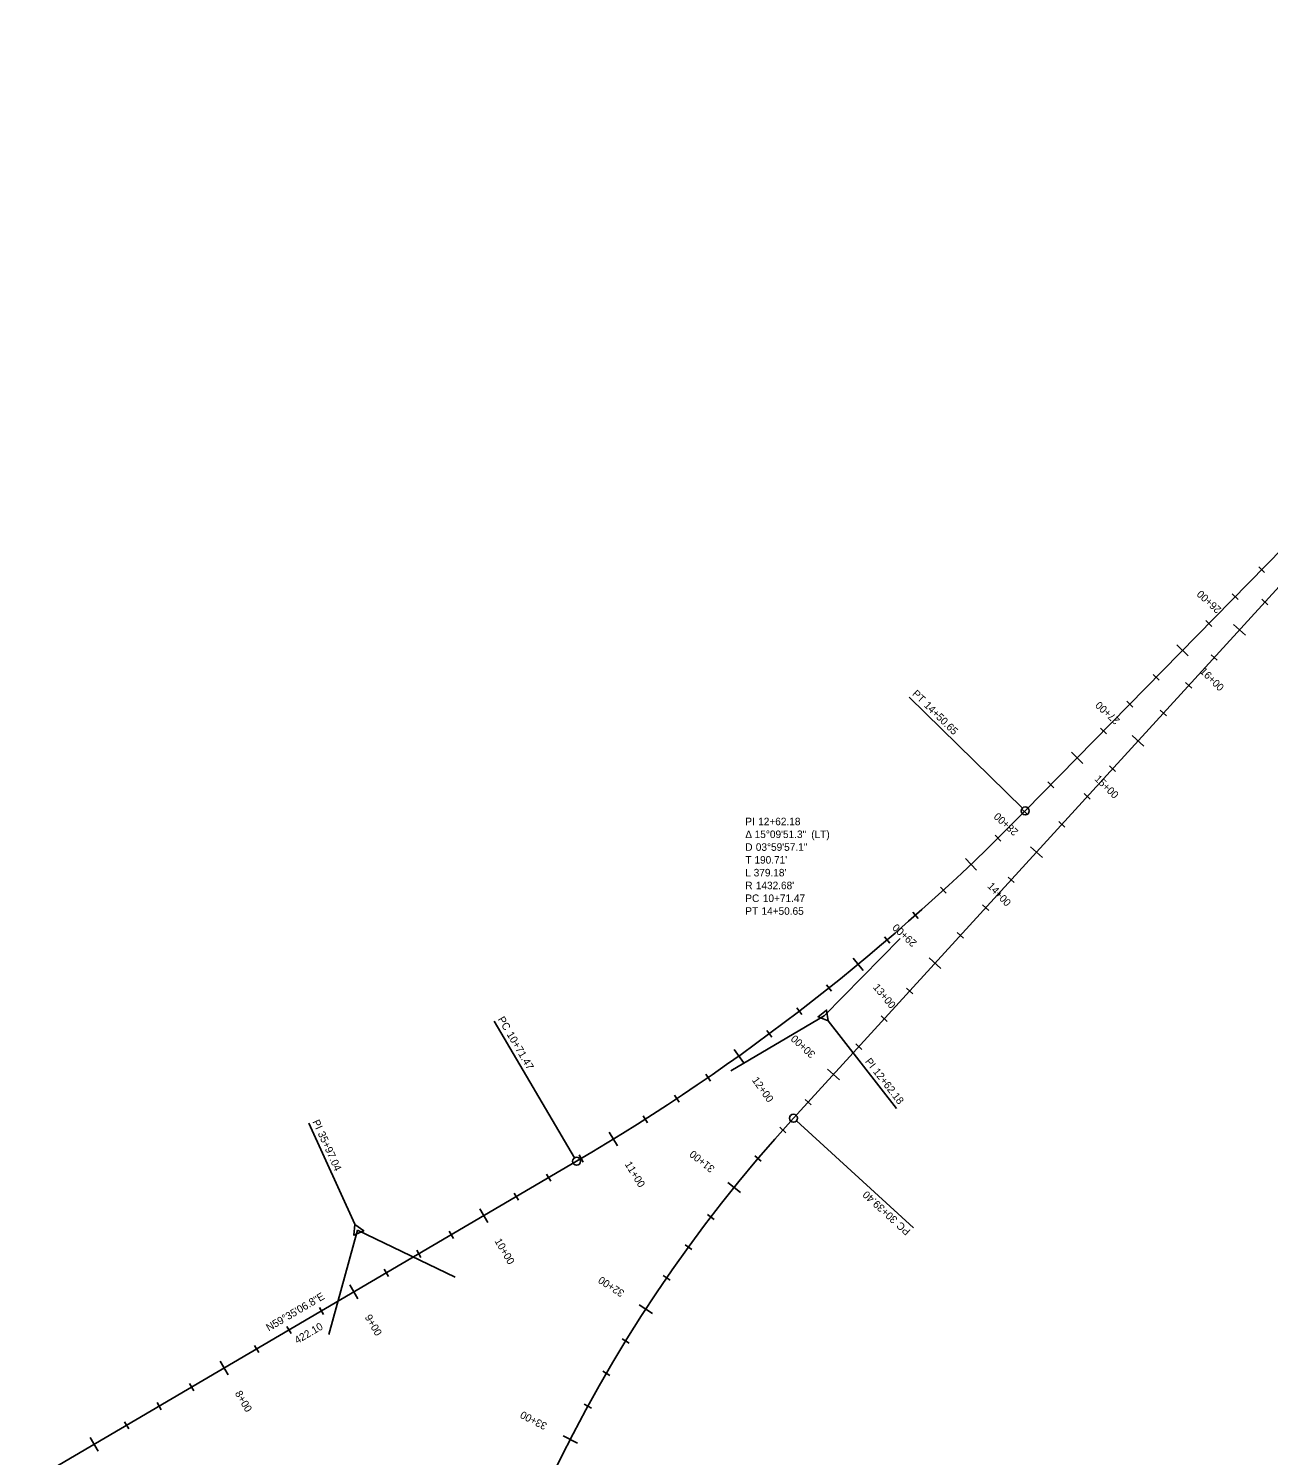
# Model space of a CAD drawing. Extents: x 2300830 to 2307917, y 756066 to 766359.
# Drawn here: x 2302935 to 2303759, y 762132 to 763080 of the extents above; entities that cross this region are included whole.
import ezdxf

# ---------------------------------------------------------------- set-up
doc = ezdxf.new("R2010")
doc.units = 0
for name, color, linetype in [('Default', 7, 'Continuous'), ('Draft_Bearing Label', 7, 'Continuous'), ('Draft_Curve Data Label', 7, 'Continuous'), ('Draft_Station Cardinal Lines', 7, 'Continuous'), ('Draft_Station Cardinal Points', 7, 'Continuous'), ('Draft_Station Labels Major', 7, 'Continuous'), ('Draft_Station Ticks Major', 7, 'Continuous'), ('Draft_Station Ticks Minor', 7, 'Continuous'), ('Geom_Baseline', 7, 'Continuous')]:
    doc.layers.add(name, color=color, linetype=linetype)

msp = doc.modelspace()

# ---------------------------------------------------------------- linework, layer by layer
at = {"layer": 'Default'}
for p, q in [((2304103.9, 763079.98), (2303443.21, 762356.01)), ((2303597.11, 762560.16), (2304068.23, 763040.89)), ((2302935.16, 762113.72), (2303299.17, 762327.41))]:
    msp.add_line(p, q, dxfattribs=at)
for centre, radius, start, end in [((2302573.87, 763562.93), 1432.68, 300.41478, 315.57902), ((2304169.7, 761693.02), 983.53, 137.61666, 272.52241)]:
    msp.add_arc(centre, radius, start, end, dxfattribs=at)
at = {"layer": 'Draft_Station Cardinal Lines'}
for p, q in [((2303595.21, 762562.03), (2303519.98, 762635.75)), ((2303463.63, 762423.95), (2303514.03, 762475.38)), ((2303297.82, 762329.71), (2303244.5, 762420.54)), ((2303463.63, 762423.95), (2303401.54, 762387.5)), ((2303466.22, 762420.64), (2303511.65, 762362.48)), ((2303151.89, 762285.5), (2303121.3, 762352.66)), ((2303445.18, 762354.21), (2303522.98, 762283.21)), ((2303153.63, 762281.68), (2303134.6, 762212.23)), ((2303153.63, 762281.68), (2303218.49, 762250.43))]:
    msp.add_line(p, q, dxfattribs=at)
for points in [[(2303466.19, 762420.68), (2303465.19, 762427.81), (2303459.52, 762423.37)], [(2303151.9, 762285.46), (2303151.21, 762278.29), (2303157.76, 762281.28)]]:
    msp.add_lwpolyline(points, close=True, dxfattribs=at)
at = {"layer": 'Draft_Station Cardinal Points'}
for p, q in [((2303519.98, 762635.75), (2303519.98, 762635.75)), ((2303597.11, 762560.16), (2303597.11, 762560.16)), ((2303244.5, 762420.54), (2303244.5, 762420.54)), ((2303463.63, 762423.95), (2303463.63, 762423.95)), ((2303511.65, 762362.48), (2303511.65, 762362.48)), ((2303121.3, 762352.66), (2303121.3, 762352.66)), ((2303443.21, 762356.01), (2303443.21, 762356.01)), ((2303299.17, 762327.41), (2303299.17, 762327.41)), ((2303153.63, 762281.68), (2303153.63, 762281.68)), ((2303522.98, 762283.21), (2303522.98, 762283.21))]:
    msp.add_line(p, q, dxfattribs=at)
for centre in [(2303597.11, 762560.16), (2303443.21, 762356.01), (2303299.17, 762327.41)]:
    msp.add_circle(centre, 2.67, dxfattribs=at)
at = {"layer": 'Draft_Station Ticks Major'}
for p, q in [((2303743.35, 762676.98), (2303735.51, 762684.13)), ((2303697.83, 762670.56), (2303705.42, 762663.13)), ((2303675.94, 762603.11), (2303668.1, 762610.27)), ((2303627.84, 762599.14), (2303635.42, 762591.71)), ((2303608.53, 762529.24), (2303600.69, 762536.4)), ((2303557.35, 762528.48), (2303564.67, 762520.79)), ((2303482.81, 762462.41), (2303489.57, 762454.22)), ((2303541.12, 762455.38), (2303533.28, 762462.54)), ((2303403.84, 762401.7), (2303410.02, 762393.06)), ((2303473.71, 762381.51), (2303465.87, 762388.67)), ((2303320.83, 762346.64), (2303326.39, 762337.59)), ((2303407.92, 762306.67), (2303399.65, 762313.33)), ((2303234.83, 762295.83), (2303240.21, 762286.67)), ((2303148.59, 762245.2), (2303153.97, 762236.04)), ((2303349.57, 762226.18), (2303340.67, 762231.97)), ((2303062.36, 762194.58), (2303067.73, 762185.42)), ((2302976.12, 762143.95), (2302981.49, 762134.79)), ((2303299.69, 762140.19), (2303290.25, 762145.04))]:
    msp.add_line(p, q, dxfattribs=at)
at = {"layer": 'Draft_Station Ticks Minor'}
for p, q in [((2303752.17, 762722.32), (2303756.11, 762718.46)), ((2303734.67, 762704.47), (2303738.61, 762700.6)), ((2303758.3, 762697.18), (2303754.22, 762700.9)), ((2303717.17, 762686.61), (2303721.11, 762682.75)), ((2303724.59, 762660.25), (2303720.51, 762663.97)), ((2303682.17, 762650.9), (2303686.12, 762647.04)), ((2303707.74, 762641.78), (2303703.66, 762645.5)), ((2303664.68, 762633.04), (2303668.62, 762629.18)), ((2303690.89, 762623.32), (2303686.81, 762627.04)), ((2303647.18, 762615.19), (2303651.12, 762611.32)), ((2303657.18, 762586.38), (2303653.11, 762590.1)), ((2303612.18, 762579.48), (2303616.12, 762575.61)), ((2303640.33, 762567.92), (2303636.25, 762571.64)), ((2303594.68, 762561.62), (2303598.63, 762557.76)), ((2303623.48, 762549.45), (2303619.4, 762553.17)), ((2303577.06, 762543.96), (2303580.93, 762540.03)), ((2303589.77, 762512.52), (2303585.7, 762516.24)), ((2303540.89, 762509.58), (2303544.63, 762505.51)), ((2303572.92, 762494.05), (2303568.85, 762497.77)), ((2303522.37, 762492.87), (2303526.03, 762488.74)), ((2303503.55, 762476.48), (2303507.14, 762472.29)), ((2303556.07, 762475.59), (2303551.99, 762479.31)), ((2303465.08, 762444.7), (2303468.52, 762440.39)), ((2303522.37, 762438.65), (2303518.29, 762442.37)), ((2303445.43, 762429.32), (2303448.79, 762424.95)), ((2303505.51, 762420.19), (2303501.44, 762423.91)), ((2303425.51, 762414.29), (2303428.8, 762409.85)), ((2303488.66, 762401.72), (2303484.58, 762405.44)), ((2303384.92, 762385.27), (2303388.05, 762380.72)), ((2303364.24, 762371.3), (2303367.3, 762366.7)), ((2303454.96, 762364.79), (2303450.88, 762368.51)), ((2303343.33, 762357.69), (2303346.3, 762353.03)), ((2303438.17, 762346.31), (2303434.05, 762349.98)), ((2303300.81, 762331.57), (2303303.62, 762326.82)), ((2303421.8, 762327.5), (2303417.59, 762331.07)), ((2303279.26, 762318.92), (2303282.05, 762314.16)), ((2303257.7, 762306.26), (2303260.49, 762301.5)), ((2303390.52, 762288.68), (2303386.14, 762292.03)), ((2303214.58, 762280.95), (2303217.37, 762276.19)), ((2303193.02, 762268.29), (2303195.81, 762263.53)), ((2303375.64, 762268.68), (2303371.17, 762271.92)), ((2303171.46, 762255.63), (2303174.25, 762250.87)), ((2303361.26, 762248.31), (2303356.71, 762251.44)), ((2303128.34, 762230.32), (2303131.14, 762225.56)), ((2303106.78, 762217.67), (2303109.58, 762212.9)), ((2303085.22, 762205.01), (2303088.02, 762200.25)), ((2303334.09, 762206.52), (2303329.39, 762209.41)), ((2303321.31, 762185.11), (2303316.53, 762187.88)), ((2303042.1, 762179.7), (2303044.9, 762174.94)), ((2303020.54, 762167.04), (2303023.34, 762162.28)), ((2303309.08, 762163.39), (2303304.23, 762166.04)), ((2302998.98, 762154.38), (2303001.78, 762149.62))]:
    msp.add_line(p, q, dxfattribs=at)
at = {"layer": 'Geom_Baseline'}
for p, q in [((2304103.9, 763079.98), (2303443.21, 762356.01)), ((2303597.11, 762560.16), (2304068.23, 763040.89)), ((2302935.16, 762113.72), (2303299.17, 762327.41))]:
    msp.add_line(p, q, dxfattribs=at)
for centre, radius, start, end in [((2302573.87, 763562.93), 1432.68, 300.41478, 315.57902), ((2304169.7, 761693.02), 983.53, 137.61666, 272.52241)]:
    msp.add_arc(centre, radius, start, end, dxfattribs=at)

# ---------------------------------------------------------------- texts
at = {"layer": 'Draft_Bearing Label'}
for s, p in [('N59°35\'06.8"E', (2303094.76, 762214.23)), ('422.10', (2303113.61, 762205.86))]:
    msp.add_text(s, height=5, rotation=30.41478, dxfattribs=at).set_placement(p)
at = {"layer": 'Draft_Curve Data Label'}
for s, p in [('PI ', (2303411.21, 762550.65)), ('12+62.18', (2303419.75, 762550.65)), ('Δ ', (2303411.21, 762542.15)), ('15°09\'51.3"', (2303417.42, 762542.15)), (' (LT)', (2303453.16, 762542.15)), ('D ', (2303411.21, 762533.65)), ('03°59\'57.1"', (2303418.19, 762533.65)), ('T ', (2303411.21, 762525.15)), ("190.71'", (2303417.29, 762525.15)), ('L ', (2303411.21, 762516.65)), ('R ', (2303411.21, 762508.15)), ("379.18'", (2303416.77, 762516.65)), ("1432.68'", (2303418.19, 762508.15)), ('PC ', (2303411.21, 762499.65)), ('10+71.47', (2303422.85, 762499.65)), ('PT ', (2303411.21, 762491.15)), ('14+50.65', (2303421.95, 762491.15))]:
    msp.add_text(s, height=5, dxfattribs=at).set_placement(p)
at = {"layer": 'Draft_Station Cardinal Points'}
for s, rotation, p in [('PT', 315.57902, (2303521.72, 762637.52)), ('14+50.65', 315.57902, (2303529.48, 762629.92)), ('PC', 300.41478, (2303246.64, 762421.8)), ('10+71.47', 300.41478, (2303252.53, 762411.76)), ('PI ', 307.9969, (2303490.49, 762393.6)), ('12+62.18', 307.9969, (2303495.75, 762386.87)), ('PI ', 294.48119, (2303123.56, 762353.69)), ('35+97.04', 294.48119, (2303127.1, 762345.92)), ('30+39.40', 137.61666, (2303512.71, 762289.22)), ('PC', 137.61666, (2303521.31, 762281.37))]:
    msp.add_text(s, height=5, rotation=rotation, dxfattribs=at).set_placement(p)
at = {"layer": 'Draft_Station Labels Major'}
for s, rotation, p in [('26+00', 137.61666, (2303727.8, 762694.56)), ('16+00', 315.57902, (2303712.75, 762652.44)), ('27+00', 137.61666, (2303660.39, 762620.69)), ('15+00', 315.57902, (2303642.76, 762581.02)), ('28+00', 137.61666, (2303592.98, 762546.82)), ('14+00', 313.55329, (2303571.62, 762509.85)), ('29+00', 137.61666, (2303525.57, 762472.96)), ('13+00', 309.55409, (2303495.74, 762442.82)), ('30+00', 137.61666, (2303458.16, 762399.09)), ('12+00', 305.55489, (2303415.38, 762381.26)), ('31+00', 141.14665, (2303391.32, 762323.26)), ('11+00', 301.55569, (2303330.92, 762325.45)), ('10+00', 300.41478, (2303244.49, 762274.43)), ('32+00', 146.97215, (2303331.37, 762241)), ('9+00', 300.41478, (2303158.25, 762223.81)), ('8+00', 300.41478, (2303072.02, 762173.18)), ('33+00', 152.79765, (2303280.08, 762153.08))]:
    msp.add_text(s, height=5, rotation=rotation, dxfattribs=at).set_placement(p)

doc.saveas('drawing.dxf')
